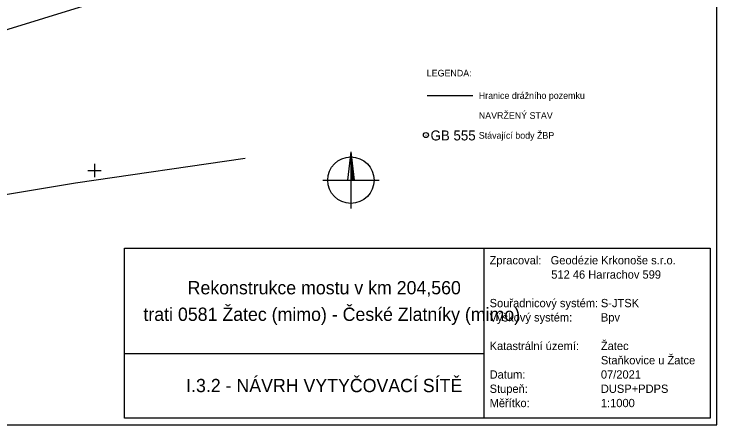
# Model space of a CAD drawing. Extents: x -800194 to -799078, y -1007177 to -1006597.
# Drawn here: x -799524.3 to -799312.4, y -1007176.6 to -1007052.9 of the extents above; entities that cross this region are included whole.
import ezdxf

# ---------------------------------------------------------------- set-up
doc = ezdxf.new("R2010")
doc.units = 0
for name, color, linetype in [('Legenda', 7, 'Continuous'), ('Legenda 1', 7, 'Continuous'), ('Legenda 2', 7, 'Continuous'), ('Ramove udaje', 7, 'Continuous'), ('Vrstva 53', 7, 'Continuous'), ('Vrstva 55', 7, 'Continuous'), ('Vrstva 63', 7, 'Continuous')]:
    doc.layers.add(name, color=color, linetype=linetype)

msp = doc.modelspace()

# ---------------------------------------------------------------- linework, layer by layer
at = {"layer": 'Legenda 1'}
for p, q in [((-799422.73, -1007094.42), (-799423.73, -1007102.92)), ((-799422.73, -1007094.42), (-799422.73, -1007111.42)), ((-799422.73, -1007094.42), (-799421.72, -1007102.92)), ((-799422.73, -1007096.55), (-799421.97, -1007102.92)), ((-799422.73, -1007098.67), (-799422.22, -1007102.92)), ((-799422.73, -1007100.8), (-799422.48, -1007102.92)), ((-799431.23, -1007102.92), (-799414.23, -1007102.92)), ((-799422.73, -1007102.92), (-799422.73, -1007102.92)), ((-799382.53, -1007174.65), (-799382.53, -1007123.39)), ((-799382.53, -1007155.25), (-799491.01, -1007155.25))]:
    msp.add_line(p, q, dxfattribs=at)
for points in [[(-800193.4, -1007176.65), (-799312.4, -1007176.65), (-799312.4, -1006766.65), (-800193.4, -1006766.65)], [(-799314.4, -1007174.65), (-799491.01, -1007174.65), (-799491.01, -1007123.39), (-799314.4, -1007123.39)]]:
    msp.add_lwpolyline(points, close=True, dxfattribs=at)
msp.add_circle((-799422.73, -1007102.92), 7, dxfattribs=at)
at = {"layer": 'Ramove udaje'}
for p, q in [((-799500, -1007098), (-799500, -1007102)), ((-799502, -1007100), (-799500, -1007100)), ((-799500, -1007100), (-799498, -1007100))]:
    msp.add_line(p, q, dxfattribs=at)
at = {"layer": 'Vrstva 53'}
msp.add_line((-799399.72, -1007077.46), (-799386.02, -1007077.46), dxfattribs=at)
at = {"layer": 'Vrstva 55'}
for points in [[(-799409.68, -1007006.29), (-799420, -1007017.54), (-799425.58, -1007022.42), (-799434.1, -1007028.26), (-799444.02, -1007032.78), (-799478.24, -1007042.75), (-799552.64, -1007065.71), (-799567.11, -1007070.01), (-799588.9, -1007077.33), (-799598.09, -1007080.87), (-799606.31, -1007085.7)], [(-799602.09, -1007115.59), (-799566.73, -1007113.9), (-799505.74, -1007103.69), (-799454.59, -1007096.36)]]:
    msp.add_lwpolyline(points, dxfattribs=at)
at = {"layer": 'Vrstva 63'}
msp.add_line((-799400.16, -1007089.36), (-799400.06, -1007089.36), dxfattribs=at)
msp.add_circle((-799400.11, -1007089.36), 0.756, dxfattribs=at)

# ---------------------------------------------------------------- texts
at = {"layer": 'Legenda'}
msp.add_text('LEGENDA:', height=2, rotation=360, dxfattribs=at).set_placement((-799399.87, -1007071.7))
at = {"layer": 'Legenda 1'}
for s, height, p in [('Zpracoval:   Geodézie Krkonoše s.r.o.', 2.5, (-799380.92, -1007128.3)), ('                    512 46 Harrachov 599', 2.5, (-799380.92, -1007132.6)), ('Rekonstrukce mostu v km 204,560', 4, (-799471.94, -1007137.32)), ('Souřadnicový systém:', 2.5, (-799380.92, -1007141.2)), ('S-JTSK', 2.5, (-799347.38, -1007141.2)), ('trati 0581 Žatec (mimo) - České Zlatníky (mimo)', 4, (-799485.27, -1007145.32)), ('Výškový systém:', 2.5, (-799380.92, -1007145.5)), ('Bpv', 2.5, (-799347.38, -1007145.5)), ('Katastrální území:', 2.5, (-799380.92, -1007154.1)), ('Žatec', 2.5, (-799347.38, -1007154.1)), ('Staňkovice u Žatce', 2.5, (-799347.38, -1007158.4)), ('I.3.2 - NÁVRH VYTYČOVACÍ SÍTĚ', 4, (-799472.39, -1007166.78)), ('Datum:', 2.5, (-799380.92, -1007162.7)), ('07/2021', 2.5, (-799347.38, -1007162.7)), ('Stupeň:', 2.5, (-799380.92, -1007167)), ('DUSP+PDPS', 2.5, (-799347.38, -1007167)), ('Měřítko:', 2.5, (-799380.92, -1007171.3)), ('1:1000', 2.5, (-799347.38, -1007171.3))]:
    msp.add_text(s, height=height, dxfattribs=at).set_placement(p)
at = {"layer": 'Legenda 2'}
for s, p in [('Hranice drážního pozemku', (-799384.18, -1007078.46)), ('NAVRŽENÝ STAV', (-799384.18, -1007084.46)), ('Stávající body ŽBP', (-799384.18, -1007090.46))]:
    msp.add_text(s, height=2, dxfattribs=at).set_placement(p)
at = {"layer": 'Vrstva 63'}
msp.add_text('GB 555', height=3, dxfattribs=at).set_placement((-799398.73, -1007090.97))

doc.saveas('drawing.dxf')
